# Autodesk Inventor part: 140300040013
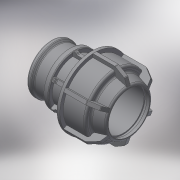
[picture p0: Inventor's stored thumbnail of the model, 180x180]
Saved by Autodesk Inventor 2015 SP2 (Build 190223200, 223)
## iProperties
Created: 2017-08
Part Number: 140300040013
Material: Generic
Description: PLASSON L.14 FEMALE ADAPTOR (SILVER) 40-1.1/4"
Document SubType Name: Modeling
Designer: KIM
Density: 1 g/cm^3
Appearance: Default
Author: KIM
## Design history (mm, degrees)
derived "140300.ipt"
feature "Solid1::140300.ipt"
tag "TaggingFeature1"
body "Solid1"
other parameters: "d2" = 73, "d4" = 15 deg, "d5" = 48.18, "d6" = 15.8994, "d9" = 38.952, "d10" = 73, "d11" = 50.6376, "d12" = 46.7424, "d13" = 54.5328, "d14" = 25, "d16" = 40.8, "d17" = 3.65, "d18" = 101, "d19" = 7.5, "d20" = 135 deg, "d21" = 7.5, "d22" = 46.7424, "d23" = 36, "d24" = 3.65, "d25" = 65.7, "d26" = 54.75, "d27" = 3.65, "d28" = 135 deg, "d29" = 2.19, "d31" = 2, "d44" = 0.8, "d45" = 1.2, "d46" = 150 deg, "d49" = 3.65, "d50" = 0, "d51" = 0.73, "d52" = 1.46, "d53" = 45 deg, "d55" = 9.348, "d56" = 3.65, "d57" = 0, "d58" = 1.2, "d61" = 360 deg, "G_" = 38.952, "E_" = 73, "H_" = 101, "l_" = 73, "l_2" = 25, "d54" = 23.37
